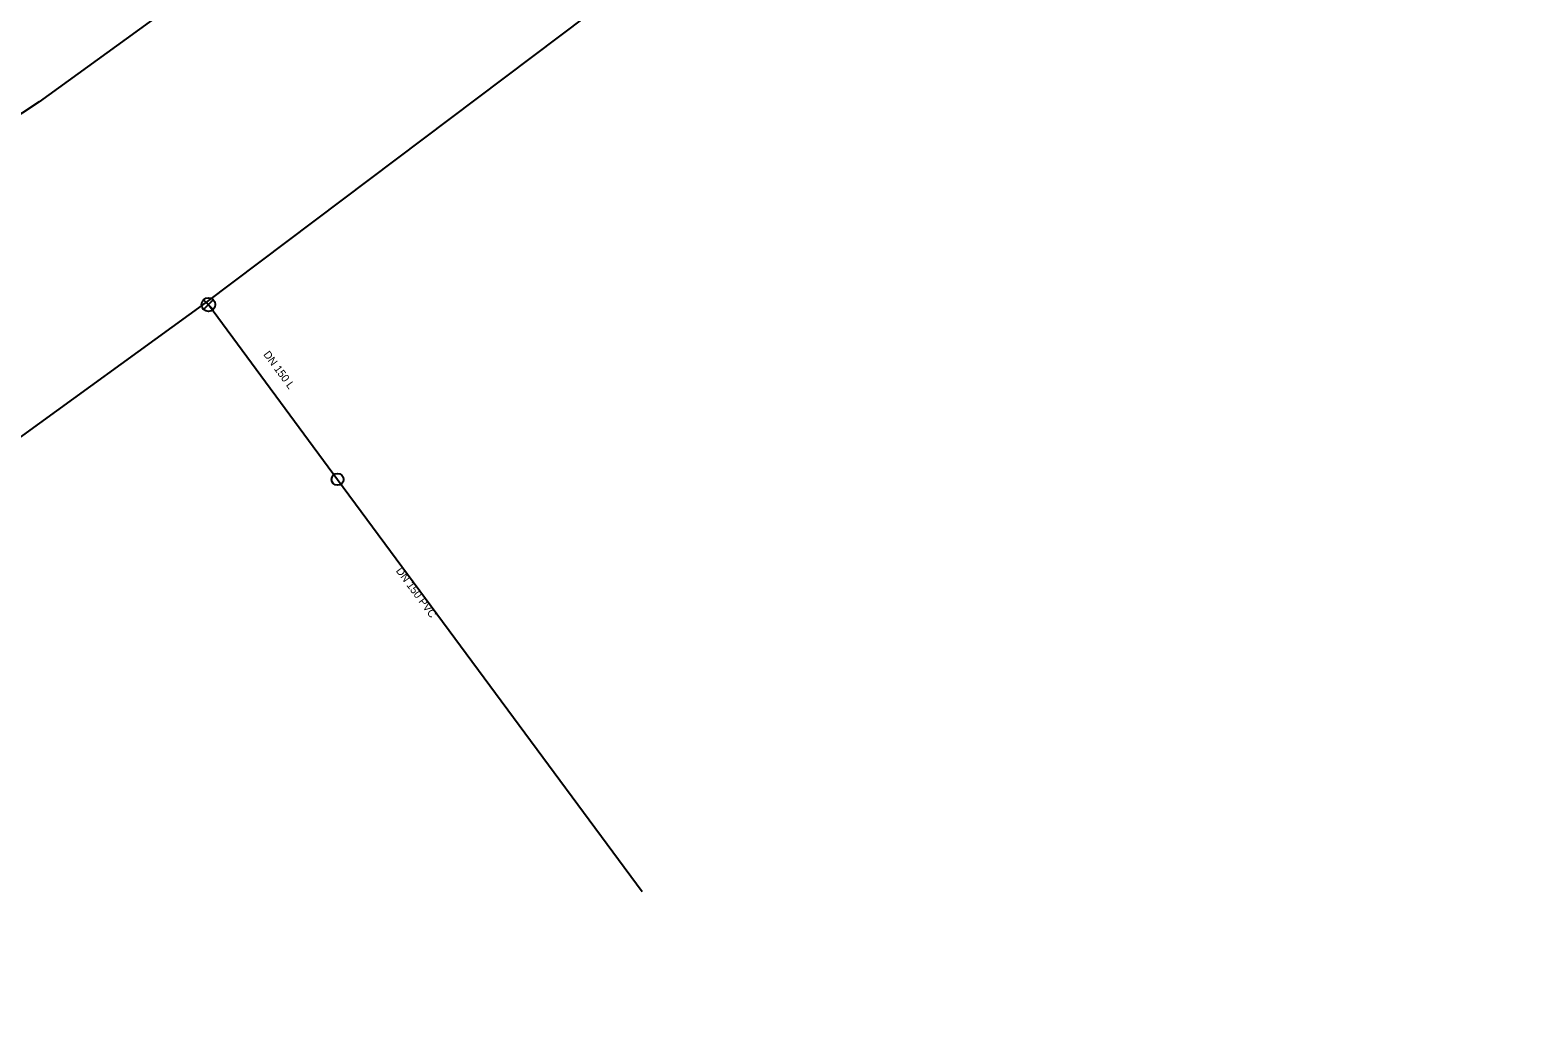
# Model space of a CAD drawing. Extents: x -451501 to -451094, y -1102108 to -1101623.
# Drawn here: x -451375.4 to -451287.1, y -1101738.2 to -1101680.8 of the extents above; entities that cross this region are included whole.
import ezdxf

# ---------------------------------------------------------------- set-up
doc = ezdxf.new("R2010")
doc.units = 0
for name, color, linetype in [('_pripojka_prevzato_z_dokumentace_', 7, 'Continuous'), ('_voda_smvak_prevzato_z_dokumentace_', 7, 'Continuous'), ('Default', 7, 'Continuous'), ('MoLevel 30', 7, 'Continuous'), ('MoLevel 53', 7, 'Continuous'), ('MoLevel 55', 7, 'Continuous')]:
    doc.layers.add(name, color=color, linetype=linetype)

# ---------------------------------------------------------------- blocks, each defined once
blk = doc.blocks.new('_uzaver_pripojka_')
at = {"layer": 'Default'}
for p, q in [((-0.000035, -0.000035), (0.000035, 0.000035)), ((0.000035, -0.000035), (-0.000035, 0.000035))]:
    blk.add_line(p, q, dxfattribs=at)
for radius in [0.00005, 0.0000025]:
    blk.add_circle((0, 0), radius, dxfattribs=at)
blk = doc.blocks.new('_sachta_voda_')
at = {"layer": 'Default'}
blk.add_circle((0, 0), 0.000035, dxfattribs=at)

msp = doc.modelspace()

# ---------------------------------------------------------------- linework, layer by layer
at = {"layer": '_pripojka_prevzato_z_dokumentace_'}
msp.add_line((-451357.413, -1101707.145), (-451339.561, -1101731.31), dxfattribs=at)
msp.add_lwpolyline([(-451365.13, -1101696.77), (-451364.98, -1101696.9), (-451357.413, -1101707.145)], dxfattribs=at)
at = {"layer": '_voda_smvak_prevzato_z_dokumentace_'}
for points in [[(-451287.07, -1101637.76), (-451298.73, -1101646.49), (-451328.51, -1101669.18), (-451365.13, -1101696.77), (-451388.63, -1101713.82), (-451391.04, -1101715.88)], [(-451352.37, -1101668.69), (-451374.89, -1101685.01), (-451391.639, -1101696.056), (-451420.33, -1101714.98), (-451434, -1101726.73), (-451445.03, -1101735.74), (-451449.89, -1101750.62)]]:
    msp.add_lwpolyline(points, dxfattribs=at)

# ---------------------------------------------------------------- block references
at = {"layer": 'MoLevel 30', "xscale": 10000, "yscale": 10000}
msp.add_blockref('_sachta_voda_', (-451357.413, -1101707.145), dxfattribs=at)
at = {"layer": 'MoLevel 53', "xscale": 7999.999999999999, "yscale": 7999.999999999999}
msp.add_blockref('_uzaver_pripojka_', (-451364.98, -1101696.9), dxfattribs=at)

# ---------------------------------------------------------------- texts
at = {"layer": 'MoLevel 55'}
for s, rotation, p in [('DN 150 L', 306.45142, (-451361.783, -1101699.828)), ('DN 150 PVC', 306.45396, (-451354.015, -1101712.51))]:
    msp.add_text(s, height=0.455, rotation=rotation, dxfattribs=at).set_placement(p)

doc.saveas('drawing.dxf')
